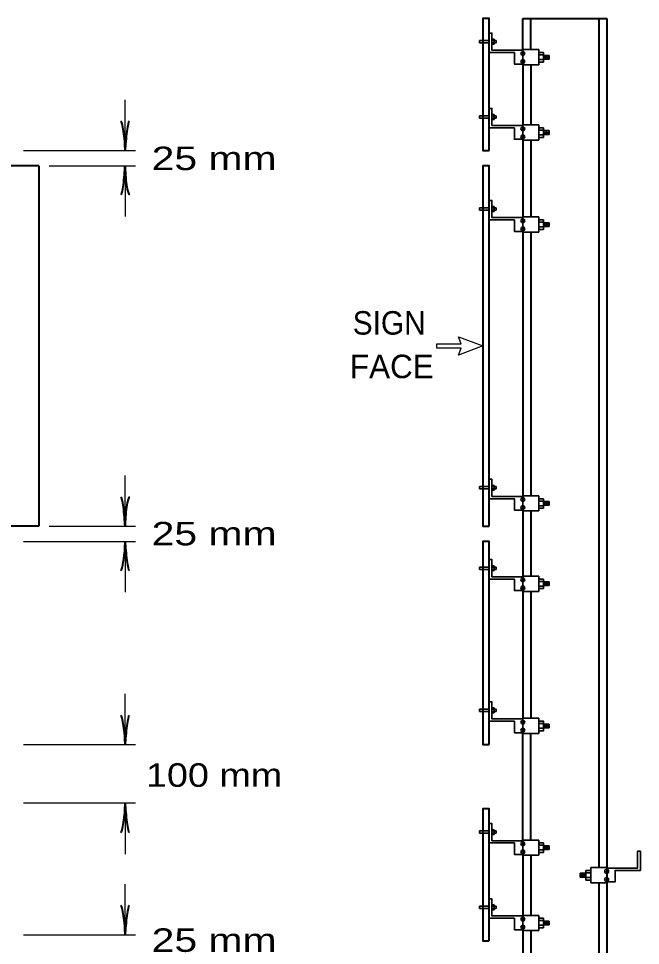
# Model space of a CAD drawing. Extents: x 851 to 1706, y -23 to 521.
# Drawn here: x 1048.4 to 1128.7, y 164.8 to 284.6 of the extents above; entities that cross this region are included whole.
import ezdxf
from ezdxf.enums import TextEntityAlignment as Align

# ---------------------------------------------------------------- set-up
doc = ezdxf.new("R2010")
doc.units = 0
doc.header["$PDMODE"] = 32
doc.header["$PDSIZE"] = 0.5
doc.layers.add('1', color=7, linetype='Continuous', lineweight=35)

msp = doc.modelspace()

# ---------------------------------------------------------------- linework, layer by layer
at = {"layer": '1', "lineweight": 40}
for p, q in [((1113.5, 284.564), (1124.325, 284.564)), ((1113.5, 280.545), (1113.5, 284.564)), ((1113.5, 284.564), (1124.325, 284.564)), ((1114.533, 280.545), (1114.533, 284.564)), ((1123.292, 284.564), (1123.292, 275.023)), ((1124.325, 284.564), (1124.325, 182.416)), ((1113.5, 278.577), (1113.5, 270.813)), ((1114.533, 278.577), (1114.533, 270.813)), ((1113.5, 268.845), (1113.5, 258.921)), ((1114.533, 268.845), (1114.533, 258.921)), ((1050.979, 265.537), (1004.396, 265.537)), ((1050.979, 265.537), (1050.979, 218.954)), ((1113.5, 256.953), (1113.5, 222.89)), ((1114.533, 256.953), (1114.533, 222.89)), ((1113.5, 220.922), (1113.5, 212.502)), ((1114.533, 220.922), (1114.533, 212.502)), ((1050.979, 218.954), (1004.396, 218.954)), ((1113.5, 210.534), (1113.5, 194.131)), ((1114.533, 210.534), (1114.533, 194.131)), ((1113.5, 182.416), (1113.5, 192.163)), ((1114.533, 182.416), (1114.533, 192.163)), ((1113.5, 178.397), (1113.5, 182.416)), ((1114.533, 178.397), (1114.533, 182.416)), ((1123.292, 182.416), (1123.292, 174.843)), ((1124.325, 182.416), (1124.325, 75.472)), ((1113.5, 176.429), (1113.5, 168.665)), ((1114.533, 176.429), (1114.533, 168.665)), ((1123.292, 172.875), (1123.292, 102.727)), ((1113.5, 166.697), (1113.5, 156.773)), ((1114.533, 166.697), (1114.533, 156.773))]:
    msp.add_line(p, q, dxfattribs=at)
at = {"layer": '1'}
for p, q in [((1107.876, 281.721), (1107.876, 281.42)), ((1109.137, 281.721), (1107.876, 281.721)), ((1109.137, 282.677), (1109.137, 280.162)), ((1109.793, 281.885), (1109.497, 281.885)), ((1110.055, 281.721), (1109.497, 281.721)), ((1109.793, 281.885), (1109.793, 281.256)), ((1110.055, 281.721), (1110.055, 281.42)), ((1109.137, 281.42), (1107.876, 281.42)), ((1110.055, 281.42), (1109.497, 281.42)), ((1109.793, 281.256), (1109.497, 281.256)), ((1113.5, 280.545), (1115.566, 280.545)), ((1113.5, 279.862), (1113.5, 280.545)), ((1115.566, 280.545), (1115.566, 278.577)), ((1113.5, 279.862), (1113.5, 279.26)), ((1113.5, 278.823), (1113.5, 279.26)), ((1115.566, 280.162), (1116.177, 280.162)), ((1115.566, 279.862), (1116.177, 279.862)), ((1115.566, 279.26), (1116.177, 279.26)), ((1116.177, 280.162), (1116.177, 278.932)), ((1116.177, 279.807), (1116.911, 279.807)), ((1116.177, 279.315), (1116.911, 279.315)), ((1116.369, 279.67), (1116.369, 279.424)), ((1116.547, 279.807), (1116.547, 279.315)), ((1116.747, 279.67), (1116.747, 279.424)), ((1116.911, 279.807), (1116.911, 279.315)), ((1113.5, 278.823), (1113.5, 278.577)), ((1113.5, 278.577), (1115.566, 278.577)), ((1115.566, 278.932), (1116.177, 278.932)), ((1107.876, 271.988), (1107.876, 271.688)), ((1109.137, 271.988), (1107.876, 271.988)), ((1109.137, 272.945), (1109.137, 270.43)), ((1109.793, 272.153), (1109.497, 272.153)), ((1110.055, 271.988), (1109.497, 271.988)), ((1109.793, 272.153), (1109.793, 271.524)), ((1110.055, 271.988), (1110.055, 271.688)), ((1109.137, 271.688), (1107.876, 271.688)), ((1110.055, 271.688), (1109.497, 271.688)), ((1109.793, 271.524), (1109.497, 271.524)), ((1113.5, 270.813), (1115.566, 270.813)), ((1113.5, 270.13), (1113.5, 270.813)), ((1115.566, 270.813), (1115.566, 268.845)), ((1113.5, 270.13), (1113.5, 269.528)), ((1115.566, 270.43), (1116.177, 270.43)), ((1115.566, 270.13), (1116.177, 270.13)), ((1116.177, 270.43), (1116.177, 269.2)), ((1116.177, 270.075), (1116.911, 270.075)), ((1116.177, 269.583), (1116.911, 269.583)), ((1116.369, 269.938), (1116.369, 269.692)), ((1116.547, 270.075), (1116.547, 269.583)), ((1116.747, 269.938), (1116.747, 269.692)), ((1116.911, 270.075), (1116.911, 269.583)), ((1113.5, 269.091), (1113.5, 269.528)), ((1113.5, 269.091), (1113.5, 268.845)), ((1113.5, 268.845), (1115.566, 268.845)), ((1115.566, 269.528), (1116.177, 269.528)), ((1115.566, 269.2), (1116.177, 269.2)), ((1107.876, 260.097), (1107.876, 259.796)), ((1109.137, 260.097), (1107.876, 260.097)), ((1109.137, 261.053), (1109.137, 258.538)), ((1109.793, 260.261), (1109.497, 260.261)), ((1110.055, 260.097), (1109.497, 260.097)), ((1109.793, 260.261), (1109.793, 259.632)), ((1110.055, 260.097), (1110.055, 259.796)), ((1109.137, 259.796), (1107.876, 259.796)), ((1110.055, 259.796), (1109.497, 259.796)), ((1109.793, 259.632), (1109.497, 259.632)), ((1113.5, 258.921), (1115.566, 258.921)), ((1113.5, 258.238), (1113.5, 258.921)), ((1115.566, 258.921), (1115.566, 256.953)), ((1113.5, 258.238), (1113.5, 257.636)), ((1113.5, 257.199), (1113.5, 257.636)), ((1115.566, 258.538), (1116.177, 258.538)), ((1115.566, 258.238), (1116.177, 258.238)), ((1115.566, 257.636), (1116.177, 257.636)), ((1116.177, 258.538), (1116.177, 257.308)), ((1116.177, 258.183), (1116.911, 258.183)), ((1116.177, 257.691), (1116.911, 257.691)), ((1116.369, 258.046), (1116.369, 257.8)), ((1116.547, 258.183), (1116.547, 257.691)), ((1116.747, 258.046), (1116.747, 257.8)), ((1116.911, 258.183), (1116.911, 257.691)), ((1113.5, 257.199), (1113.5, 256.953)), ((1113.5, 256.953), (1115.566, 256.953)), ((1115.566, 257.308), (1116.177, 257.308)), ((1107.876, 224.066), (1107.876, 223.765)), ((1109.137, 224.066), (1107.876, 224.066)), ((1109.137, 225.023), (1109.137, 222.508)), ((1109.793, 224.23), (1109.497, 224.23)), ((1110.055, 224.066), (1109.497, 224.066)), ((1109.793, 224.23), (1109.793, 223.601)), ((1110.055, 224.066), (1110.055, 223.765)), ((1109.137, 223.765), (1107.876, 223.765)), ((1110.055, 223.765), (1109.497, 223.765)), ((1109.793, 223.601), (1109.497, 223.601)), ((1113.5, 222.89), (1115.566, 222.89)), ((1113.5, 222.207), (1113.5, 222.89)), ((1115.566, 222.89), (1115.566, 220.922)), ((1113.5, 222.207), (1113.5, 221.606)), ((1115.566, 222.508), (1116.177, 222.508)), ((1115.566, 222.207), (1116.177, 222.207)), ((1116.177, 222.508), (1116.177, 221.277)), ((1116.177, 222.152), (1116.911, 222.152)), ((1116.177, 221.66), (1116.911, 221.66)), ((1116.369, 222.016), (1116.369, 221.77)), ((1116.547, 222.152), (1116.547, 221.66)), ((1116.747, 222.016), (1116.747, 221.77)), ((1116.911, 222.152), (1116.911, 221.66)), ((1113.5, 221.168), (1113.5, 221.606)), ((1113.5, 221.168), (1113.5, 220.922)), ((1113.5, 220.922), (1115.566, 220.922)), ((1115.566, 221.606), (1116.177, 221.606)), ((1115.566, 221.277), (1116.177, 221.277)), ((1109.137, 214.634), (1109.137, 212.119)), ((1107.876, 213.678), (1107.876, 213.377)), ((1109.137, 213.678), (1107.876, 213.678)), ((1109.137, 213.377), (1107.876, 213.377)), ((1109.793, 213.842), (1109.497, 213.842)), ((1110.055, 213.678), (1109.497, 213.678)), ((1110.055, 213.377), (1109.497, 213.377)), ((1109.793, 213.842), (1109.793, 213.213)), ((1110.055, 213.678), (1110.055, 213.377)), ((1109.793, 213.213), (1109.497, 213.213)), ((1113.5, 212.502), (1115.566, 212.502)), ((1113.5, 211.819), (1113.5, 212.502)), ((1115.566, 212.502), (1115.566, 210.534)), ((1115.566, 212.119), (1116.177, 212.119)), ((1116.177, 212.119), (1116.177, 210.889)), ((1113.5, 211.819), (1113.5, 211.217)), ((1113.5, 210.78), (1113.5, 211.217)), ((1115.566, 211.819), (1116.177, 211.819)), ((1115.566, 211.217), (1116.177, 211.217)), ((1115.566, 210.889), (1116.177, 210.889)), ((1116.177, 211.764), (1116.911, 211.764)), ((1116.177, 211.272), (1116.911, 211.272)), ((1116.369, 211.627), (1116.369, 211.381)), ((1116.547, 211.764), (1116.547, 211.272)), ((1116.747, 211.627), (1116.747, 211.381)), ((1116.911, 211.764), (1116.911, 211.272)), ((1113.5, 210.78), (1113.5, 210.534)), ((1113.5, 210.534), (1115.566, 210.534)), ((1107.876, 195.307), (1107.876, 195.006)), ((1109.137, 195.307), (1107.876, 195.307)), ((1109.137, 196.264), (1109.137, 193.749)), ((1109.793, 195.471), (1109.497, 195.471)), ((1110.055, 195.307), (1109.497, 195.307)), ((1109.793, 195.471), (1109.793, 194.842)), ((1110.055, 195.307), (1110.055, 195.006)), ((1109.137, 195.006), (1107.876, 195.006)), ((1110.055, 195.006), (1109.497, 195.006)), ((1109.793, 194.842), (1109.497, 194.842)), ((1113.5, 194.131), (1115.566, 194.131)), ((1113.5, 193.448), (1113.5, 194.131)), ((1115.566, 194.131), (1115.566, 192.163)), ((1113.5, 193.448), (1113.5, 192.846)), ((1115.566, 193.448), (1116.177, 193.448)), ((1116.177, 193.393), (1116.911, 193.393)), ((1116.177, 192.901), (1116.911, 192.901)), ((1116.369, 193.256), (1116.369, 193.01)), ((1116.547, 193.393), (1116.547, 192.901)), ((1116.747, 193.256), (1116.747, 193.01)), ((1116.911, 193.393), (1116.911, 192.901)), ((1113.5, 192.409), (1113.5, 192.846)), ((1113.5, 192.409), (1113.5, 192.163)), ((1113.5, 192.163), (1115.566, 192.163)), ((1115.566, 192.846), (1116.177, 192.846)), ((1109.137, 180.53), (1109.137, 178.015)), ((1109.793, 179.737), (1109.497, 179.737)), ((1109.793, 179.737), (1109.793, 179.108)), ((1107.876, 179.573), (1107.876, 179.272)), ((1109.137, 179.573), (1107.876, 179.573)), ((1109.137, 179.272), (1107.876, 179.272)), ((1110.055, 179.573), (1109.497, 179.573)), ((1110.055, 179.272), (1109.497, 179.272)), ((1109.793, 179.108), (1109.497, 179.108)), ((1110.055, 179.573), (1110.055, 179.272)), ((1113.5, 178.397), (1115.566, 178.397)), ((1113.5, 177.714), (1113.5, 178.397)), ((1113.5, 177.714), (1113.5, 177.113)), ((1115.566, 178.397), (1115.566, 176.429)), ((1115.566, 178.015), (1116.177, 178.015)), ((1115.566, 177.714), (1116.177, 177.714)), ((1116.177, 178.015), (1116.177, 176.784)), ((1116.177, 177.659), (1116.911, 177.659)), ((1116.369, 177.523), (1116.369, 177.276)), ((1116.547, 177.659), (1116.547, 177.167)), ((1116.747, 177.523), (1116.747, 177.276)), ((1116.911, 177.659), (1116.911, 177.167)), ((1113.5, 176.675), (1113.5, 177.113)), ((1113.5, 176.675), (1113.5, 176.429)), ((1113.5, 176.429), (1115.566, 176.429)), ((1115.566, 177.113), (1116.177, 177.113)), ((1115.566, 176.784), (1116.177, 176.784)), ((1116.177, 177.167), (1116.911, 177.167)), ((1128.688, 176.976), (1128.688, 174.461)), ((1121.648, 174.105), (1120.913, 174.105)), ((1120.913, 174.105), (1120.913, 173.613)), ((1121.078, 173.969), (1121.078, 173.723)), ((1121.278, 174.105), (1121.278, 173.613)), ((1121.456, 173.969), (1121.456, 173.723)), ((1122.259, 174.461), (1121.648, 174.461)), ((1121.648, 174.461), (1121.648, 173.231)), ((1122.259, 174.16), (1121.648, 174.16)), ((1124.325, 174.844), (1122.259, 174.844)), ((1122.259, 174.844), (1122.259, 172.875)), ((1124.325, 174.16), (1124.325, 174.844)), ((1124.325, 174.16), (1124.325, 173.559)), ((1121.648, 173.613), (1120.913, 173.613)), ((1122.259, 173.559), (1121.648, 173.559)), ((1122.259, 173.231), (1121.648, 173.231)), ((1124.325, 172.875), (1122.259, 172.875)), ((1124.325, 173.121), (1124.325, 173.559)), ((1124.325, 173.121), (1124.325, 172.875)), ((1109.137, 170.798), (1109.137, 168.282)), ((1107.876, 169.841), (1107.876, 169.54)), ((1109.137, 169.841), (1107.876, 169.841)), ((1109.137, 169.54), (1107.876, 169.54)), ((1109.793, 170.005), (1109.497, 170.005)), ((1110.055, 169.841), (1109.497, 169.841)), ((1110.055, 169.54), (1109.497, 169.54)), ((1109.793, 169.376), (1109.497, 169.376)), ((1109.793, 170.005), (1109.793, 169.376)), ((1110.055, 169.841), (1110.055, 169.54)), ((1113.5, 168.665), (1115.566, 168.665)), ((1113.5, 167.982), (1113.5, 168.665)), ((1113.5, 167.982), (1113.5, 167.38)), ((1115.566, 168.665), (1115.566, 166.697)), ((1115.566, 168.282), (1116.177, 168.282)), ((1115.566, 167.982), (1116.177, 167.982)), ((1116.177, 168.282), (1116.177, 167.052)), ((1116.177, 167.927), (1116.911, 167.927)), ((1116.369, 167.79), (1116.369, 167.544)), ((1116.547, 167.927), (1116.547, 167.435)), ((1116.747, 167.79), (1116.747, 167.544)), ((1116.911, 167.927), (1116.911, 167.435)), ((1113.5, 166.943), (1113.5, 167.38)), ((1113.5, 166.943), (1113.5, 166.697)), ((1113.5, 166.697), (1115.566, 166.697)), ((1115.566, 167.38), (1116.177, 167.38)), ((1115.566, 167.052), (1116.177, 167.052)), ((1116.177, 167.435), (1116.911, 167.435))]:
    msp.add_line(p, q, dxfattribs=at)
at = {"layer": '1', "lineweight": 25}
for p, q in [((1062.132, 267.505), (1062.132, 274.066)), ((1049.01, 267.505), (1063.445, 267.505)), ((1052.291, 265.537), (1063.445, 265.537)), ((1062.132, 265.537), (1062.132, 258.976)), ((1062.132, 218.954), (1062.132, 225.515)), ((1052.291, 218.954), (1063.445, 218.954)), ((1049.01, 216.985), (1063.445, 216.985)), ((1062.132, 216.985), (1062.132, 210.424)), ((1062.132, 190.714), (1062.132, 197.275)), ((1049.01, 190.741), (1063.445, 190.741)), ((1049.01, 183.196), (1063.445, 183.196)), ((1062.132, 183.132), (1062.132, 176.571)), ((1062.132, 166.138), (1062.132, 172.698)), ((1049.01, 166.138), (1063.445, 166.138))]:
    msp.add_line(p, q, dxfattribs=at)
at = {"layer": '1', "lineweight": 40}
for points in [[(1109.137, 267.505), (1109.137, 284.564), (1108.307, 284.564), (1108.307, 267.505)], [(1109.137, 218.954), (1109.137, 265.537), (1108.307, 265.537), (1108.307, 218.954)], [(1109.137, 190.741), (1109.137, 216.985), (1108.307, 216.985), (1108.307, 190.741)], [(1109.137, 165.357), (1109.137, 182.416), (1108.307, 182.416), (1108.307, 165.357)]]:
    msp.add_lwpolyline(points, close=True, dxfattribs=at)
at = {"layer": '1', "lineweight": 25}
for points in [[(1109.137, 282.677), (1109.497, 282.677), (1109.497, 280.463)], [(1109.137, 272.945), (1109.497, 272.945), (1109.497, 270.731)], [(1109.137, 261.053), (1109.497, 261.053), (1109.497, 258.839)], [(1109.137, 225.023), (1109.497, 225.023), (1109.497, 222.808)], [(1109.137, 214.634), (1109.497, 214.634), (1109.497, 212.42)], [(1109.137, 214.634), (1109.497, 214.634), (1109.497, 212.42)], [(1109.137, 196.264), (1109.497, 196.264), (1109.497, 194.049)], [(1109.137, 180.53), (1109.497, 180.53), (1109.497, 178.315)], [(1109.137, 170.798), (1109.497, 170.798), (1109.497, 168.583)]]:
    msp.add_lwpolyline(points, dxfattribs=at)
at = {"layer": '1'}
for points in [[(1109.137, 282.677), (1109.497, 282.677), (1109.497, 280.463), (1113.5, 280.463)], [(1113.5, 278.686), (1112.417, 278.686), (1112.417, 280.162), (1109.137, 280.162)], [(1109.137, 272.945), (1109.497, 272.945), (1109.497, 270.731), (1113.5, 270.731)], [(1113.5, 268.954), (1112.417, 268.954), (1112.417, 270.43), (1109.137, 270.43)], [(1109.137, 261.053), (1109.497, 261.053), (1109.497, 258.839), (1113.5, 258.839)], [(1113.5, 257.062), (1112.417, 257.062), (1112.417, 258.538), (1109.137, 258.538)], [(1109.137, 225.023), (1109.497, 225.023), (1109.497, 222.808), (1113.5, 222.808)], [(1113.5, 221.031), (1112.417, 221.031), (1112.417, 222.508), (1109.137, 222.508)], [(1109.137, 214.634), (1109.497, 214.634), (1109.497, 212.42), (1113.5, 212.42)], [(1113.5, 210.643), (1112.417, 210.643), (1112.417, 212.119), (1109.137, 212.119)], [(1109.137, 196.264), (1109.497, 196.264), (1109.497, 194.049), (1113.5, 194.049)], [(1113.5, 192.272), (1112.417, 192.272), (1112.417, 193.749), (1109.137, 193.749)], [(1115.566, 193.749), (1116.177, 193.749), (1116.177, 192.518), (1115.566, 192.518)], [(1109.137, 180.53), (1109.497, 180.53), (1109.497, 178.315), (1113.5, 178.315)], [(1113.5, 176.538), (1112.417, 176.538), (1112.417, 178.015), (1109.137, 178.015)], [(1128.688, 176.976), (1128.327, 176.976), (1128.327, 174.762), (1124.325, 174.762)], [(1124.325, 172.985), (1125.408, 172.985), (1125.408, 174.461), (1128.688, 174.461)], [(1109.137, 170.798), (1109.497, 170.798), (1109.497, 168.583), (1113.5, 168.583)], [(1113.5, 166.806), (1112.417, 166.806), (1112.417, 168.282), (1109.137, 168.282)]]:
    msp.add_lwpolyline(points, dxfattribs=at)
at = {"layer": '1', "lineweight": 40}
msp.add_lwpolyline([(1123.292, 275.023), (1123.292, 202.907), (1123.292, 182.416)], dxfattribs=at)
at = {"layer": '1', "lineweight": 25}
msp.add_lwpolyline([(1105.518, 241.945), (1102.402, 241.945), (1102.402, 242.519), (1105.518, 242.519), (1105.163, 243.421), (1108.307, 242.245), (1105.163, 241.042)], close=True, dxfattribs=at)
at = {"layer": '1', "lineweight": 40}
for centre, major_axis, ratio, start_param, end_param in [((1061.757, 268.943), (0.205, -2.343), 0.122415, 0.8963533, 3.1415927), ((1061.757, 268.943), (0.205, -2.343), 0.122415, 0.8963533, 3.1415927), ((1062.398, 268.981), (-0.23, -2.305), 0.07063, 3.1407148, 5.41811), ((1062.398, 268.981), (-0.23, -2.305), 0.07063, 3.1407148, 5.41811), ((1061.842, 264.072), (0.23, 2.305), 0.07063, 3.1407148, 5.41811), ((1061.842, 264.072), (0.23, 2.305), 0.07063, 3.1407148, 5.41811), ((1062.482, 264.111), (-0.205, 2.343), 0.122415, 0.8963533, 3.1415927), ((1062.482, 264.111), (-0.205, 2.343), 0.122415, 0.8963533, 3.1415927), ((1061.842, 220.43), (0.23, -2.305), 0.07063, 0.8650754, 3.1424706), ((1061.842, 220.43), (0.23, -2.305), 0.07063, 0.8650754, 3.1424706), ((1062.482, 220.391), (-0.205, -2.343), 0.122415, 3.1415927, 5.386832), ((1062.482, 220.391), (-0.205, -2.343), 0.122415, 3.1415927, 5.386832), ((1061.757, 215.559), (0.205, 2.343), 0.122415, 3.1415927, 5.386832), ((1061.757, 215.559), (0.205, 2.343), 0.122415, 3.1415927, 5.386832), ((1062.398, 215.521), (-0.23, 2.305), 0.07063, 0.8650754, 3.1424706), ((1062.398, 215.521), (-0.23, 2.305), 0.07063, 0.8650754, 3.1424706), ((1061.757, 192.135), (0.205, -2.343), 0.122415, 0.8963533, 3.1415927), ((1062.398, 192.174), (-0.23, -2.305), 0.07063, 3.1407148, 5.41811), ((1061.757, 181.711), (0.205, 2.343), 0.122415, 3.1415927, 5.386832), ((1062.398, 181.672), (-0.23, 2.305), 0.07063, 0.8650754, 3.1424706), ((1061.757, 167.575), (0.205, -2.343), 0.122415, 0.8963533, 3.1415927), ((1061.757, 167.575), (0.205, -2.343), 0.122415, 0.8963533, 3.1415927), ((1062.398, 167.614), (-0.23, -2.305), 0.07063, 3.1407148, 5.41811), ((1062.398, 167.614), (-0.23, -2.305), 0.07063, 3.1407148, 5.41811)]:
    msp.add_ellipse(centre, major_axis=major_axis, ratio=ratio, start_param=start_param, end_param=end_param, dxfattribs=at)
at = {"layer": '1'}
for p in [(1113.5, 280.053), (1113.5, 279.014), (1113.5, 270.321), (1113.5, 269.282), (1113.5, 258.429), (1113.5, 257.39), (1113.5, 222.398), (1113.5, 221.359), (1113.5, 212.01), (1113.5, 210.971), (1113.5, 193.639), (1113.5, 192.6), (1113.5, 177.905), (1113.5, 176.866), (1124.325, 174.351), (1124.325, 173.313), (1113.5, 168.173), (1113.5, 167.134)]:
    msp.add_point(p, dxfattribs=at)

# ---------------------------------------------------------------- texts
for s, width, p in [('25 mm', 1.3, (1073.615, 264.975)), ('SIGN', 0.95, (1096.237, 243.712)), ('25 mm', 1.3, (1073.615, 216.478)), ('100 mm', 1.2, (1073.615, 185.274)), ('25 mm', 1.3, (1073.615, 163.944))]:
    msp.add_text(s, height=3.037, dxfattribs=dict(at, width=width)).set_placement(p, align=Align.CENTER)
msp.add_text('FACE', height=3.037, dxfattribs=at).set_placement((1096.573, 238.087), align=Align.CENTER)

doc.saveas('drawing.dxf')
